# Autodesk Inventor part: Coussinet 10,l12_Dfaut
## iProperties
Created: 2007-07
Part Number: Coussinet 10,l12_Dfaut
Document SubType Name: Modeling
Designer: EF
Density: 1 g/cm^3
Author: EF
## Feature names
1. Base1
